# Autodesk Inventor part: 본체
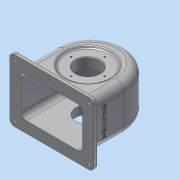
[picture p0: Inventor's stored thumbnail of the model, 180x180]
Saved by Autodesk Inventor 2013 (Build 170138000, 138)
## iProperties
Created: 2016-01
Part Number: 본체
Material: 알루미늄 6061
Document SubType Name: Modeling
Designer: Administrator
Density: 2.71 g/cm^3
Mass: 827.356 g
Surface Area: 1006.17 cm^2
Volume: 305.298 cm^3
Author: Administrator
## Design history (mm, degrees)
sketch "스케치1"
  geometry: L1 (-70, -53)-(70, -53); L2 (70, -53)-(70, -60); L3 (70, -60)-(-70, -60); L4 (-70, -60)-(-70, -53); L5 (-70, -53)-(70, -60); L6 (70, -53)-(-70, -60); L7 (-57, 4)-(-57, -53); L8 (57, 4)-(57, -53); C1 r 51 at (0, 4); A1 r 57 centre (0, 4) between (57, 4) and (-57, 4); 3 further points
  constraints: 16 end point, 3 midpoint, 3 parallel, 2 centre point, 2 perpendicular, 2 point on circle, 2 point on line, 2 tangent, 2 vertical alignment, 1 horizontal
  dimensions: "d0" = 140 distance of L2.end L3.end; "d1" = 7 distance of L1.end L2.end; "d2" = 60 distance from line of point (0, 0) L3; "d3" = 102 diameter of C1; "d4" = 64 distance from line of L3 C1.centre; "d6" = 6 radial gap between concentric circles of C1 A1
extrude "돌출1" new body sketch "스케치1" stored distance "d7" = 77; taper "d8" = 0 deg
extrude "돌출2" join sketch "스케치1" stored distance "d9" = 104; taper "d10" = 0 deg
feature "쉘1" dims "d11" = 6, "d12" = 5
sketch "스케치2"
  geometry: L1 (57, -38.5)-(-57, -38.5) reference; L2 (-57, -38.5)-(-57, 38.5) reference; L3 (-57, 38.5)-(57, 38.5) reference; L4 (57, 38.5)-(57, -38.5) reference; L5 (-51, 33.5)-(-51, -33.5) reference; L6 (-51, -33.5)-(51, -33.5) reference; L7 (51, -33.5)-(51, 33.5) reference; L8 (51, 33.5)-(-51, 33.5) reference; L9 (-51, 33.5)-(51, 33.5); L10 (51, 33.5)-(51, -33.5); L11 (51, -33.5)-(-51, -33.5); L12 (-51, -33.5)-(-51, 33.5); 1 further point
  constraints: 8 end point, 2 parallel, 1 horizontal, 1 perpendicular
extrude "돌출3" cut sketch "스케치2" stored distance "d13" = 10; taper "d14" = 0 deg
sketch "스케치3"
  geometry: C1 r 31 at (0, 0); 1 further point
  constraints: 1 centre point, 1 coincident
  dimensions: "d15" = 62 diameter of C1
extrude "돌출4" join sketch "스케치3" distance "d16" = 10; taper "d17" = 0 deg
hole "구멍1" diameter "d20" = 40; stored, may be unused: countersink angle "d24" = 90 deg, drill point angle "d26" = 0 deg; dims "d18" = 10, "d19" = 10, "d21" = 6, "d22" = 4, "d23" = 2, "d25" = 15
chamfer "모따기1" distance "d27" = 1; stored, may be unused: second distance "d28" = 2, angle "d29" = 45 deg
sketch "스케치4" dims "d30" = 48
  geometry: C1 r 31 at (0, 0) reference; C2 r 21 at (0, 0) reference; 2 further points
  constraints: 2 vertical alignment, 1 coincident, 2 other
hole "구멍2" sketch "스케치4" at (0, 24) diameter "d31" = 2.459; stored, may be unused: countersink angle "d35" = 90 deg, drill point angle "d37" = 118 deg; dims "d32" = 6, "d33" = 4, "d34" = 2, "d36" = 8
fillet "모깎기1" dims "d41" = 14
fillet "모깎기2" dims "d42" = 9
node "작업 평면1"
sketch "스케치5"
  geometry: C1 r 6 at (0, 0); 1 further point
  constraints: 1 centre point, 1 coincident
  dimensions: "d44" = 12 diameter of C1
extrude "돌출5" join sketch "스케치5" stored distance "d45" = 10; taper "d46" = 0 deg
fillet "모깎기3" dims "d47" = 3
hole "구멍3" diameter "d50" = 4.459; stored, may be unused: countersink angle "d54" = 90 deg, drill point angle "d56" = 118 deg; dims "d48" = 10, "d49" = 10, "d51" = 6, "d52" = 4, "d53" = 2, "d55" = 8
fillet "모깎기4" dims "d57" = 8
fillet "모깎기5" dims "d58" = 3
sketch "스케치6"
  geometry: 3 further points
  dimensions: "d59" = 44 vertical distance of point (62, -49) point (0, -5); "d60" = 62 horizontal distance of point (62, -49) point (0, -5); "d61" = 124 distance of point (124, -5) point (0, -5); "d62" = 44 vertical distance of point (124, -5) point (62, -49)
hole "구멍4" sketch "스케치6" at (0, -5), (124, -5) diameter "d63" = 5; stored, may be unused: countersink angle "d67" = 90 deg, drill point angle "d69" = 0 deg; dims "d64" = 6, "d65" = 4, "d66" = 2, "d68" = 7
node "작업 평면2"
sketch "스케치7"
  geometry: C1 r 28 at (0, -4); 1 further point
  constraints: 1 centre point, 1 coincident
  dimensions: "d74" = 56 diameter of C1
extrude "돌출6" join sketch "스케치7" stored distance "d75" = 10; taper "d76" = 40 deg
fillet "모깎기6" dims "d77" = 3
sketch "스케치8"
  geometry: L1 (64, 6)-(67, 6) reference; L2 (67, 6)-(67, 2.229) reference; L3 (67, 2.229)-(55, 2.229) reference; L4 (55, 2.229)-(55, 24.5) reference; L5 (46, 33.5)-(41.426, 33.5) reference; L6 (41.426, 33.5)-(28, 17.5) reference; L7 (28, 17.5)-(-28, 17.5) reference; L8 (-28, 17.5)-(-41.426, 33.5) reference; L9 (-41.426, 33.5)-(-60, 33.5) reference; L10 (-60, 33.5)-(-60, 52) reference; L11 (-60, 52)-(-56, 52) reference; L12 (-53, 49)-(-53, 38.5) reference; L13 (-53, 38.5)-(47, 38.5) reference; L14 (61, 24.5)-(61, 9) reference; L15 (-20, -47.5)-(-21, -48.5) reference; L16 (-21, -48.5)-(-22.771, -48.5) reference; L17 (-22.771, -48.5)-(-22.771, -40.5) reference; L18 (-22.771, -40.5)-(-24, -39.761) reference; L19 (-24, -39.761)-(-25.23, -40.5) reference; L20 (-25.23, -40.5)-(-25.23, -48.5) reference; L21 (-25.23, -48.5)-(-31, -48.5) reference; L22 (-31, -48.5)-(-31, -41.5) reference; L23 (-34, -38.5)-(-53, -38.5) reference; L24 (-53, -38.5)-(-53, -49) reference; L25 (-56, -52)-(-60, -52) reference; L26 (-60, -52)-(-60, -33.5) reference; L27 (-60, -33.5)-(-20, -33.5) reference; L28 (-20, -33.5)-(-20, -47.5) reference; L29 (21, -48.5)-(20, -47.5) reference; L30 (20, -47.5)-(20, -33.5) reference; L31 (20, -33.5)-(46, -33.5) reference; L32 (55, -24.5)-(55, -2.229) reference; L33 (55, -2.229)-(67, -2.229) reference; L34 (67, -2.229)-(67, -6) reference; L35 (67, -6)-(64, -6) reference; L36 (61, -9)-(61, -24.5) reference; L37 (47, -38.5)-(34, -38.5) reference; L38 (31, -41.5)-(31, -48.5) reference; L39 (31, -48.5)-(25.23, -48.5) reference; L40 (25.23, -48.5)-(25.23, -40.5) reference; L41 (25.23, -40.5)-(24, -39.761) reference; L42 (24, -39.761)-(22.771, -40.5) reference; L43 (22.771, -40.5)-(22.771, -48.5) reference; L44 (22.771, -48.5)-(21, -48.5) reference; L45 (39.094, 38.5)-(36.577, 35.5); L46 (36.577, 35.5)-(0, 35.5); L47 (39.094, 38.5)-(0, 38.5); L48 (0, 38.5)-(0, 35.5); A1 r 9 centre (46, 24.5) between (55, 24.5) and (46, 33.5) reference; A2 r 3 centre (-56, 49) between (-53, 49) and (-56, 52) reference; A3 r 14 centre (47, 24.5) between (61, 24.5) and (47, 38.5) reference; A4 r 3 centre (-34, -41.5) between (-31, -41.5) and (-34, -38.5) reference; A5 r 3 centre (-56, -49) between (-56, -52) and (-53, -49) reference; A6 r 9 centre (46, -24.5) between (46, -33.5) and (55, -24.5) reference; A7 r 14 centre (47, -24.5) between (47, -38.5) and (61, -24.5) reference; A8 r 3 centre (34, -41.5) between (34, -38.5) and (31, -41.5) reference; 2 further points
  constraints: 8 end point, 2 parallel, 2 point on line, 1 midpoint, 1 perpendicular, 1 vertical alignment, 2 other
  dimensions: "d78" = 5 distance between parallel lines of L45 L6; "d79" = 3 distance between parallel lines of L13 L46
revolve "회전1" sketch "스케치8" stored, may be unused: angle "d80" = 90 deg
sketch "스케치9"
  geometry: C1 r 36.577 at (0, 0) reference; C2 r 20 at (0, 0)
  constraints: 1 centre point, 1 coincident
  dimensions: "d81" = 40 diameter of C2
extrude "돌출7" cut sketch "스케치9" stored distance "d82" = 10; taper "d83" = 0 deg
sketch "스케치10" dims "d84" = 56
  geometry: C1 r 20 at (0, 0) reference; C2 r 36.577 at (0, 0) reference; 2 further points
  constraints: 2 vertical alignment, 1 coincident, 2 other
hole "구멍5" sketch "스케치10" at (0, 28) diameter "d85" = 2.459; stored, may be unused: countersink angle "d89" = 90 deg, drill point angle "d91" = 118 deg; dims "d86" = 7, "d87" = 4, "d88" = 2, "d90" = 9
chamfer "모따기2" distance "d95" = 1; stored, may be unused: second distance "d96" = 2, angle "d97" = 45 deg
fillet "모깎기7" dims "d98" = 3
chamfer "모따기3" distance "d99" = 1; stored, may be unused: second distance "d100" = 2, angle "d101" = 45 deg
sketch "스케치11"
  geometry: L1 (-63, 57)-(-63, 0) reference; L2 (19.5, -7)-(-68.5, -7) reference; 2 further points
  constraints: 1 other
  dimensions: "d102" = 38.5 distance from line of L1 point (-24.5, 23); "d103" = 30 distance from line of L2 point (-24.5, 23)
feature "엠보싱1" sketch "스케치11" dims "d104" = 0.5, "d105" = 0
node "솔리드1"
pattern_circular "원형 패턴1" dims angle "d39" = 360 deg
pattern_linear "직사각형 패턴1" dims "d72" = 88
pattern_circular "원형 패턴2" dims angle "d93" = 360 deg
node "절단 모서리 투영1"
node "절단 모서리 투영2"
other parameters: "d43" = 67, "d73" = 16
